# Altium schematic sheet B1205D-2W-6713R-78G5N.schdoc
size 277 x 190 mm; Device: default297x210; Symbol: default297x210; Name: default297x210; Size: "A4"; Id: /; File: EV_CMP6713R_07B_01; Sheet: /
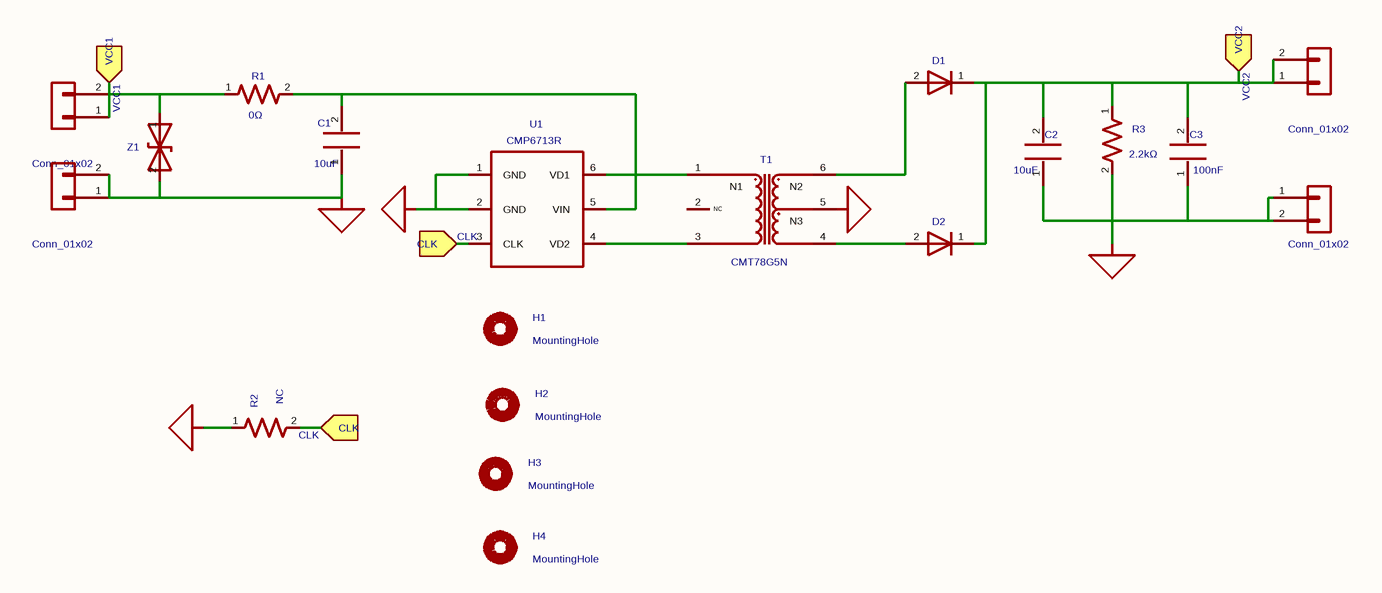
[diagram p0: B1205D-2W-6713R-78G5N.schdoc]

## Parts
C1  10uF  [MYLibrary:C0805]
C2  10uF  [MYLibrary:C0805]
C3  100nF  [MYLibrary:C0603]
D1  DSK24  [MYLibrary:SOD-123-323]  (value not drawn)
D2  DSK24  [MYLibrary:SOD-123-323]  (value not drawn)
H1  value MountingHole  [MountingHole:MountingHole_3.2mm_M3]  (hidden comment: Mechanical_MountingHole)
H2  value MountingHole  [MountingHole:MountingHole_3.2mm_M3]  (hidden comment: Mechanical_MountingHole)
H3  value MountingHole  [MountingHole:MountingHole_3.2mm_M3]  (hidden comment: Mechanical_MountingHole)
H4  value MountingHole  [MountingHole:MountingHole_3.2mm_M3]  (hidden comment: Mechanical_MountingHole)
J1  value Conn_01x02  [Connector_PinHeader_2.54mm:PinHeader_1x02_P2.54mm_Vertical]  (hidden comment: HX PZ2.54-1x2P ZZ)
J2  value Conn_01x02  [Connector_PinHeader_2.54mm:PinHeader_1x02_P2.54mm_Vertical]  (hidden comment: HX PZ2.54-1x2P ZZ)
J3  value Conn_01x02  [Connector_PinHeader_2.54mm:PinHeader_1x02_P2.54mm_Vertical]  (hidden comment: HX PZ2.54-1x2P ZZ)
J4  value Conn_01x02  [Connector_PinHeader_2.54mm:PinHeader_1x02_P2.54mm_Vertical]  (hidden comment: HX PZ2.54-1x2P ZZ)
R1  0Ω  [MYLibrary:R0805]
R2  value NC  [MYLibrary:R0603]  (hidden comment: My_Library_R)
R3  2.2kΩ  [MYLibrary:R0603]
T1  CMT78G5N  [My Library:CMT78G5N]
U1  CMP6713R  [My Library:CMP6713R]
Z1  Diode_SMAJ30CA  [MYLibrary:SOD-123-323]  (value not drawn)

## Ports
CLK (in), VCC1 (in), VCC2 (in)

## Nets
GND1: C1.1 J2.1(Pin_1) J2.2(Pin_2) R2.1 U1.1(GND) U1.2(GND) Z1.2(A2)
GND2: C2.1 C3.1 J4.1(Pin_1) J4.2(Pin_2) R3.2 T1.5
CLK: R2.2 U1.3(CLK) ; port CLK
VCC1: J1.1(Pin_1) J1.2(Pin_2) R1.1 Z1.1(A1) ; port VCC1
VCC2: C2.2 C3.2 D1.1(K) D2.1(K) J3.1(Pin_1) J3.2(Pin_2) R3.1 ; port VCC2
NetC1_2: C1.2 R1.2 U1.5(VIN)
NetD1_2: D1.2(A) T1.6
NetD2_2: D2.2(A) T1.4
NetT1_1: T1.1 U1.6(VD1)
NetT1_3: T1.3 U1.4(VD2)

Not connected (* = marked no-connect by the designer): T1 2

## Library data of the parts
C1 = CC0805KKX5R8BB106_C89831: 容值:10uF;精度:±10%;额定电压:25V;温度系数:X5R;; Manufacturer: YAGEO(国巨); Symbol: My_Library_C; Add into BOM: yes; 3D Model: 1ba041120af144c991958decab20d241; 3D Model Transform: 78.74,51.181,0,0,0,0,0,0.0005,0; Tolerance: ±10%; Voltage Rating: 25V; Temperature Coefficient: X5R; ki_keywords: cap capacitor; ki_fp_filters: C_*; UniqueId: 5fb4f22ffcb6a001; ModelName: C0805_L2.0-W1.3-H1.3
C2 = CC0805KKX5R6BB106: 容值:10uF;精度:±10%;额定电压:10V;材质(温度系数):X5R;; Manufacturer: YAGEO(国巨); Symbol: My_Library_C; Add into BOM: yes; 3D Model: 1ba041120af144c991958decab20d241; 3D Model Transform: 78.74,51.181,0,0,0,0,0,0.0005,0; Tolerance: ±10%; Voltage Rated: 10V; Temperature Coefficient: X5R; ki_keywords: cap capacitor; ki_fp_filters: C_*; UniqueId: 21d50210554cb61f; ModelName: C0805_L2.0-W1.3-H1.3
C3 = CC0603KRX7R9BB104: 容值:100nF;精度:±10%;额定电压:50V;温度系数:X7R;; Manufacturer: YAGEO(国巨); Symbol: My_Library_C; Add into BOM: yes; 3D Model: ac125912035d415993ca9572d50418b1; 3D Model Transform: 62.992,31.496,0,0,0,0,0,0,0; Tolerance: ±10%; Voltage Rating: 50V; Temperature Coefficient: X7R; ki_keywords: cap capacitor; ki_fp_filters: C_*; UniqueId: ec64484c8c07847f; ModelName: C0603_L1.6-W0.8-H0.8
D1 = DSK24_C64890: 二极管配置:独立式;正向压降(Vf):550mV@2A;直流反向耐压(Vr):40V;整流电流:2A;; Manufacturer: MDD(辰达半导体); Symbol: My_Library_D; Add into BOM: yes; 3D Model: 7884390a25fb4c08947731ebfba7e3f8; 3D Model Transform: 144.8816,62.992,0,0,0,0,0,0,0; Diode Configuration: 独立式; Voltage - DC Reverse(Vr): 40V; Current - Rectified: 2A; Reverse Leakage Current (Ir): 500uA@40V; Operating Junction Temperature Range: -55℃~+150℃; Value: D; ki_keywords: diode; ki_fp_filters: TO-???* *_Diode_* *SingleDiode* D_*; UniqueId: 07a0d5848cd81316; ModelName: SOD-123_L2.8-W1.8-LS3.7-RD
D2 = DSK24_C64890: 二极管配置:独立式;正向压降(Vf):550mV@2A;直流反向耐压(Vr):40V;整流电流:2A;; Manufacturer: MDD(辰达半导体); Symbol: My_Library_D; Add into BOM: yes; 3D Model: 7884390a25fb4c08947731ebfba7e3f8; 3D Model Transform: 144.8816,62.992,0,0,0,0,0,0,0; Diode Configuration: 独立式; Voltage - DC Reverse(Vr): 40V; Current - Rectified: 2A; Reverse Leakage Current (Ir): 500uA@40V; Operating Junction Temperature Range: -55℃~+150℃; Value: D; ki_keywords: diode; ki_fp_filters: TO-???* *_Diode_* *SingleDiode* D_*; UniqueId: fa5cd661465da5bc; ModelName: SOD-123_L2.8-W1.8-LS3.7-RD
H1-H4 = Mechanical_MountingHole: Mounting Hole without connection; ki_fp_filters: MountingHole*; Attribute1: H3; AddInBom: yes
J1 = HX PZ2.54-1x2P ZZ: 插针结构:1x2P;间距:2.54mm;行距:-;圆针/方针:方针;安装方式:直插;排数:单排;总PIN位数:2P;额定电流:3A;额定电压:1kV;配合针长度:6mm;塑高:2.5mm;端接针长度:3mm;触头材质:黄铜;触头镀层:金;工作温度:-40℃~+105℃;颜色:黑色;; Manufacturer: hanxia(韩下); Symbol: Connector_Generic_Conn_01x02; Add into BOM: yes; 3D Model: c7a9f3c3e6e34627af2bf939e464cb35; 3D Model Transform: 200,100,0,0,0,0,0,0,-118.11; Pin Structure: 1x2P; Pitch: 2.54mm; Circluar Pins/Square Pins: 方针; Current Rating: 3A; Voltage Rating (Max): 1kV; ki_keywords: connector; ki_fp_filters: Connector*:*_1x??_*; UniqueId: 9f49826860c2c79d; ModelName: HDR-TH_2P-P2.54-M-LI-1X2P
J2 = HX PZ2.54-1x2P ZZ: 插针结构:1x2P;间距:2.54mm;行距:-;圆针/方针:方针;安装方式:直插;排数:单排;总PIN位数:2P;额定电流:3A;额定电压:1kV;配合针长度:6mm;塑高:2.5mm;端接针长度:3mm;触头材质:黄铜;触头镀层:金;工作温度:-40℃~+105℃;颜色:黑色;; Manufacturer: hanxia(韩下); Symbol: Connector_Generic_Conn_01x02; Add into BOM: yes; 3D Model: c7a9f3c3e6e34627af2bf939e464cb35; 3D Model Transform: 200,100,0,0,0,0,0,0,-118.11; Pin Structure: 1x2P; Pitch: 2.54mm; Circluar Pins/Square Pins: 方针; Current Rating: 3A; Voltage Rating (Max): 1kV; ki_keywords: connector; ki_fp_filters: Connector*:*_1x??_*; UniqueId: 42913bc3a3449998; ModelName: HDR-TH_2P-P2.54-M-LI-1X2P
J3 = HX PZ2.54-1x2P ZZ: 插针结构:1x2P;间距:2.54mm;行距:-;圆针/方针:方针;安装方式:直插;排数:单排;总PIN位数:2P;额定电流:3A;额定电压:1kV;配合针长度:6mm;塑高:2.5mm;端接针长度:3mm;触头材质:黄铜;触头镀层:金;工作温度:-40℃~+105℃;颜色:黑色;; Manufacturer: hanxia(韩下); Symbol: Connector_Generic_Conn_01x02; Add into BOM: yes; 3D Model: c7a9f3c3e6e34627af2bf939e464cb35; 3D Model Transform: 200,100,0,0,0,0,0,0,-118.11; Pin Structure: 1x2P; Pitch: 2.54mm; Circluar Pins/Square Pins: 方针; Current Rating: 3A; Voltage Rating (Max): 1kV; ki_keywords: connector; ki_fp_filters: Connector*:*_1x??_*; UniqueId: 6ca7fcf0d18ad80e; ModelName: HDR-TH_2P-P2.54-M-LI-1X2P
J4 = HX PZ2.54-1x2P ZZ: 插针结构:1x2P;间距:2.54mm;行距:-;圆针/方针:方针;安装方式:直插;排数:单排;总PIN位数:2P;额定电流:3A;额定电压:1kV;配合针长度:6mm;塑高:2.5mm;端接针长度:3mm;触头材质:黄铜;触头镀层:金;工作温度:-40℃~+105℃;颜色:黑色;; Manufacturer: hanxia(韩下); Symbol: Connector_Generic_Conn_01x02; Add into BOM: yes; 3D Model: c7a9f3c3e6e34627af2bf939e464cb35; 3D Model Transform: 200,100,0,0,0,0,0,0,-118.11; Pin Structure: 1x2P; Pitch: 2.54mm; Circluar Pins/Square Pins: 方针; Current Rating: 3A; Voltage Rating (Max): 1kV; ki_keywords: connector; ki_fp_filters: Connector*:*_1x??_*; UniqueId: 048fde32f53a6793; ModelName: HDR-TH_2P-P2.54-M-LI-1X2P
R1 = RC0805FR-070RL: 电阻类型:厚膜电阻;阻值:0Ω;精度:±1%;功率:125mW;工作电压:150V;温度系数:-;; Manufacturer: YAGEO(国巨); Symbol: My_Library_R; Add into BOM: yes; 3D Model: fc143cca1e79419f9cd78b61e9279f08; 3D Model Transform: 78.74,51.181,0,0,0,0,0,-0.0005,0; Tolerance: ±1%; Power(Watts): 125mW; Voltage-Supply(Max): 150V; ki_keywords: R res resistor; ki_fp_filters: R_*; UniqueId: 4e166b190d4de1c3; ModelName: R0805_L2.0-W1.3-H0.6
R2 = My_Library_R: Add into BOM: no; ki_keywords: R res resistor; ki_fp_filters: R_*; UniqueId: 06442d24ab060343; Attribute1: R2
R3 = RC0603FR-072K2L: 电阻类型:厚膜电阻;阻值:2.2kΩ;精度:±1%;功率:100mW;工作电压:75V;温度系数:±100ppm/℃;; Manufacturer: YAGEO(国巨); Symbol: My_Library_R; Add into BOM: yes; 3D Model: fc143cca1e79419f9cd78b61e9279f08; 3D Model Transform: 31.8897,63.7794,0,90,0,0,0,0,0; Tolerance: ±1%; Power(Watts): 100mW; Voltage-Supply(Max): 75V; ki_keywords: R res resistor; ki_fp_filters: R_*; UniqueId: 6e26aea592918673; ModelName: R0603
T1 = CMT78G5N: 电源变压器 SMD-6 隔离耐压：2.5KV 一次绕组：单路 二次绕组：双路 功率5W; Manufacturer: coileasy(线易); Symbol: Library_CMT78G5N; Add into BOM: yes; Origin Footprint: MYLibrary:CMT3-6-7; UniqueId: cf2c480e5945250c
U1 = CMP6713R: CMP6713R 是全桥式变压器驱动器，芯片内部集成两 个 N 型 功 率 MOSFET 和 两 个 P 型 功 率MOSFET，通过内部振荡器提供具有精准时序和死区时间的互补驱动信号。驱动器搭配配套的变压器，可以实现输入电压 6.5V-30V, 输出功率不超过2W 的隔离电源。采用不同的变压器，外围只需搭配简单的输入输出滤波电容，隔离变压器和整流电路，即可获得多种电压的非稳压输出。产品提供电阻选频功能，可以在 200-420 kHz 范围内连续调整开关频率，并且同时实现抖频。; Manufacturer: coileasy(线易); Symbol: Library_CMP6713R; Add into BOM: yes; 3D Model: 18da8f6c14a34920b3e136b5c401a119; 3D Model Transform: 110.236,113.364,0,90,0,0,0.0005,0.0005,0; Origin Footprint: Package_TO_SOT_SMD:SOT-23-6; UniqueId: 48a4a086d8c42a18; ModelName: SOT-23-6_L2.9-W1.6-H1.5-LS2.8-P0.95
Z1 = Diode_SMAJ30CA: 400W bidirectional Transient Voltage Suppressor, 30.0Vr, SMA(DO-214AC); Value: SMF28CA; Add into BOM: no; ki_keywords: bidirectional diode TVS voltage suppressor; ki_fp_filters: D*SMA*; Origin Footprint: Diode_SMD:D_SMA; UniqueId: d022797895385730; Attribute1: Z1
